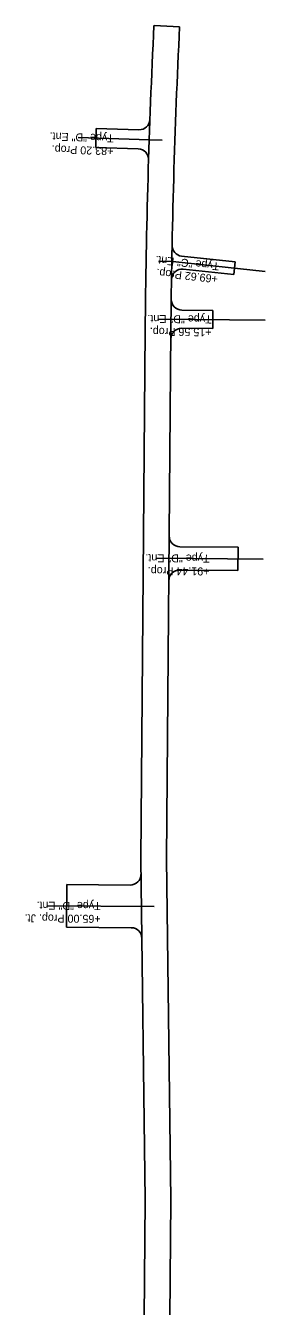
# Model space of a CAD drawing. Extents: x 15298968 to 15307577, y 8935228 to 8937628.
# Drawn here: x 15302201 to 15302425, y 8936428 to 8937628 of the extents above; entities that cross this region are included whole.
import ezdxf

# ---------------------------------------------------------------- set-up
doc = ezdxf.new("R2010")
doc.units = 0
for name, color, linetype in [('brgPreStructureNew', 7, 'Continuous'), ('conCulvert', 7, 'Continuous'), ('Dimension', 7, 'Continuous'), ('G Prop 6 Valve (B1) CELL', 7, 'Continuous')]:
    doc.layers.add(name, color=color, linetype=linetype)

msp = doc.modelspace()

# ---------------------------------------------------------------- linework, layer by layer
at = {"layer": 'brgPreStructureNew'}
msp.add_line((15302345, 8937626.8), (15302321.1, 8937628), dxfattribs=at)
at = {"layer": 'conCulvert'}
for p, q in [((15302316.8, 8937521.1), (15302250.2, 8937523.3)), ((15302328.6, 8937520.7), (15302316.8, 8937521.1)), ((15302325.7, 8937407.2), (15302338.7, 8937407)), ((15302338.7, 8937407), (15302425.2, 8937397.7)), ((15302325, 8937353.1), (15302425, 8937352.1)), ((15302323.1, 8937129), (15302423.1, 8937128.2)), ((15302321.3, 8936802.6), (15302221.3, 8936803.4))]:
    msp.add_line(p, q, dxfattribs=at)
at = {"layer": 'G Prop 6 Valve (B1) CELL'}
for p, q in [((15302267, 8937531.7), (15302266.6, 8937513.8)), ((15302307, 8937530.4), (15302267, 8937531.7)), ((15302306.4, 8937512.5), (15302266.6, 8937513.8)), ((15302346.9, 8937412.1), (15302397.1, 8937406.7)), ((15302395.8, 8937394.8), (15302397.1, 8937406.7)), ((15302348.5, 8937399.9), (15302395.8, 8937394.8)), ((15302347.1, 8937361.4), (15302376.2, 8937361.1)), ((15302376, 8937344.1), (15302376.2, 8937361.1)), ((15302346.9, 8937344.4), (15302376, 8937344.1)), ((15302345.2, 8937139.8), (15302399.7, 8937139.4)), ((15302399.7, 8937139.4), (15302399.5, 8937117.4)), ((15302345, 8937117.8), (15302399.5, 8937117.4)), ((15302239.6, 8936823.3), (15302239.3, 8936783.3)), ((15302298.8, 8936822.8), (15302239.6, 8936823.3)), ((15302299.8, 8936782.8), (15302239.3, 8936783.3))]:
    msp.add_line(p, q, dxfattribs=at)
for points in [[(15302312.9, 8937342.1), (15302308.7, 8936847.1), (15302312.8, 8936527.8), (15302306.6, 8935787.9), (15302299.8, 8935563.3)], [(15302336.9, 8937341.9), (15302332.7, 8936847.2), (15302336.8, 8936527.8), (15302330.6, 8935787.5), (15302323.1, 8935541.5)]]:
    msp.add_lwpolyline(points, dxfattribs=at)
for centre, radius, start, end in [((15309368.8, 8937283), 7056.2, 177.19698, 179.51965), ((15309368.8, 8937283), 7032.2, 177.19698, 179.51965), ((15302307.3, 8937540.4), 10, 268.1388, 357.39), ((15302306, 8937502.5), 10, 358.2199, 88.1388), ((15302348, 8937422), 10, 178.8651, 263.8705), ((15302347.4, 8937389.9), 10, 83.8705, 179.1272), ((15302347.2, 8937371.4), 10, 179.2783, 269.4292), ((15302300.9, 8937342.3), 12, 359.5197, 359.5208), ((15302346.8, 8937334.4), 10, 89.4292, 179.5196), ((15302345.3, 8937149.8), 10, 179.5196, 269.5196), ((15302344.9, 8937107.8), 10, 89.5196, 179.5196), ((15302298.9, 8936832.8), 10, 269.5196, 359.5197), ((15302299.7, 8936772.8), 10, 359.5197, 89.5196)]:
    msp.add_arc(centre, radius, start, end, dxfattribs=at)

# ---------------------------------------------------------------- texts
at = {"layer": 'Dimension'}
for s, rotation, p in [('Type "D" Ent.', 178.1388, (15302283.6, 8937526)), ('+83.20 Prop.', 178.1388, (15302283.2, 8937514)), ('Type "C" Ent.', 173.8705, (15302382.4, 8937406)), ('+69.62 Prop.', 173.8705, (15302381.1, 8937394.1)), ('Type "D" Ent.', 179.4292, (15302375, 8937356.4)), ('+15.56 Prop.', 179.4292, (15302374.9, 8937344.4)), ('Type "D" Ent.', 179.5196, (15302373.1, 8937132.3)), ('+91.44 Prop.', 179.5196, (15302373, 8937120.3)), ('Type "D" Ent.', 179.5196, (15302271.3, 8936806.8)), ('+65.00 Prop. Jt.', 179.5196, (15302271.2, 8936794.8))]:
    msp.add_text(s, height=7.5, rotation=rotation, dxfattribs=at).set_placement(p)

doc.saveas('drawing.dxf')
